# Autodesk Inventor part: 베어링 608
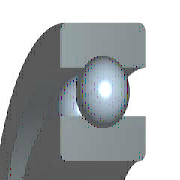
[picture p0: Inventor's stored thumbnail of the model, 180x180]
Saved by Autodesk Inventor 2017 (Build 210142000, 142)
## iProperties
IsCustomPart: 1
Created: 2012-02
Part Number: 베어링 608
Material: 강철, 연강
Description: 깊은 그루브 볼 베어링
Document SubType Name: Modeling
Standard: KS B 2023
Designer: mduedu
Standards Organization: KS
Language: ko-KR
Size Designation: 608 - 8 x 22 x 7
Categories: <MemberInstance><Categories><Category DisplayName="샤프트 부품" InternalName="7f7aeb1f-a693-4053-b835-cee3144e0d98" Mnemonic="SHFT"><Category DisplayName="베어링" Inter
Density: 7.86 g/cm^3
Mass: 12.1605 g
Surface Area: 20.0754 cm^2
Volume: 1.54714 cm^3
Appearance: 노란색
Author: mduedu
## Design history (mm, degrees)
sketch "스케치" dims "d0" = 3.64 (= -0.26 x WD + 0.26 x BD)
  geometry: L1 (1.68, 7.5)-(5.32, 7.5); L2 (3.5, 7.5)-(3.5, 5.68); L3 (3.5, 7.5)-(3.5, 9.32); L4 (2.148, 6.282)-(0, 6.282); L5 (0, 4)-(7, 4); L6 (2.148, 8.718)-(0, 8.718); L7 (0, 11)-(7, 11); L8 (7, 4)-(7, 6.282); L9 (4.852, 6.282)-(7, 6.282); L10 (4.852, 8.718)-(7, 8.718); L11 (7, 11)-(7, 8.718); L12 (-1.4, 0)-(8.4, 0) reference; L13 (0, -0.3)-(0, 5.3) reference
  constraints: 22 end point, 4 point on line, 2 collinear, 2 perpendicular, 2 symmetric about line, 1 midpoint, 1 parallel, 14 other
  dimensions: "d9" = 8 diameter of L5 L12 (= WD); "d11" = 22 diameter of L7 L12 (= BD); "d12" = 7 distance between parallel lines of L8 L13 (= KB); "d13" = 12.564 diameter of L9 L12 (= 0.326 x BD + 0.674 x WD)
revolve "본체" stored, may be unused: angle "d6" = 90 deg
revolve "볼" stored, may be unused: angle "d7" = 90 deg
pattern_circular "IDS_ARRAYBALL[SIMPL:T]" dims angle "d3" = 360 deg
body "Solid1"
fillet "모깎기1" dims "d1" = 0.3 (= KRS)
other parameters: "WD" = 8 [user parameter; used in 5 equation terms], "BD" = 22 [user parameter; used in 5 equation terms], "KB" = 7 [user parameter; used in 1 equation term], "KRS" = 0.3 [user parameter; used in 1 equation term], "d4" = 0, "d5" = 0, "d8" = 0, "d14" = 0, "d15" = 0, "BBA" = 0 [user parameter], "BC0" = 1370000 [user parameter], "BC" = 3250000 [user parameter], "BR" = 11 (= 0.5 x BD) [user parameter], "WR" = 4 (= 0.5 x WD) [user parameter]
